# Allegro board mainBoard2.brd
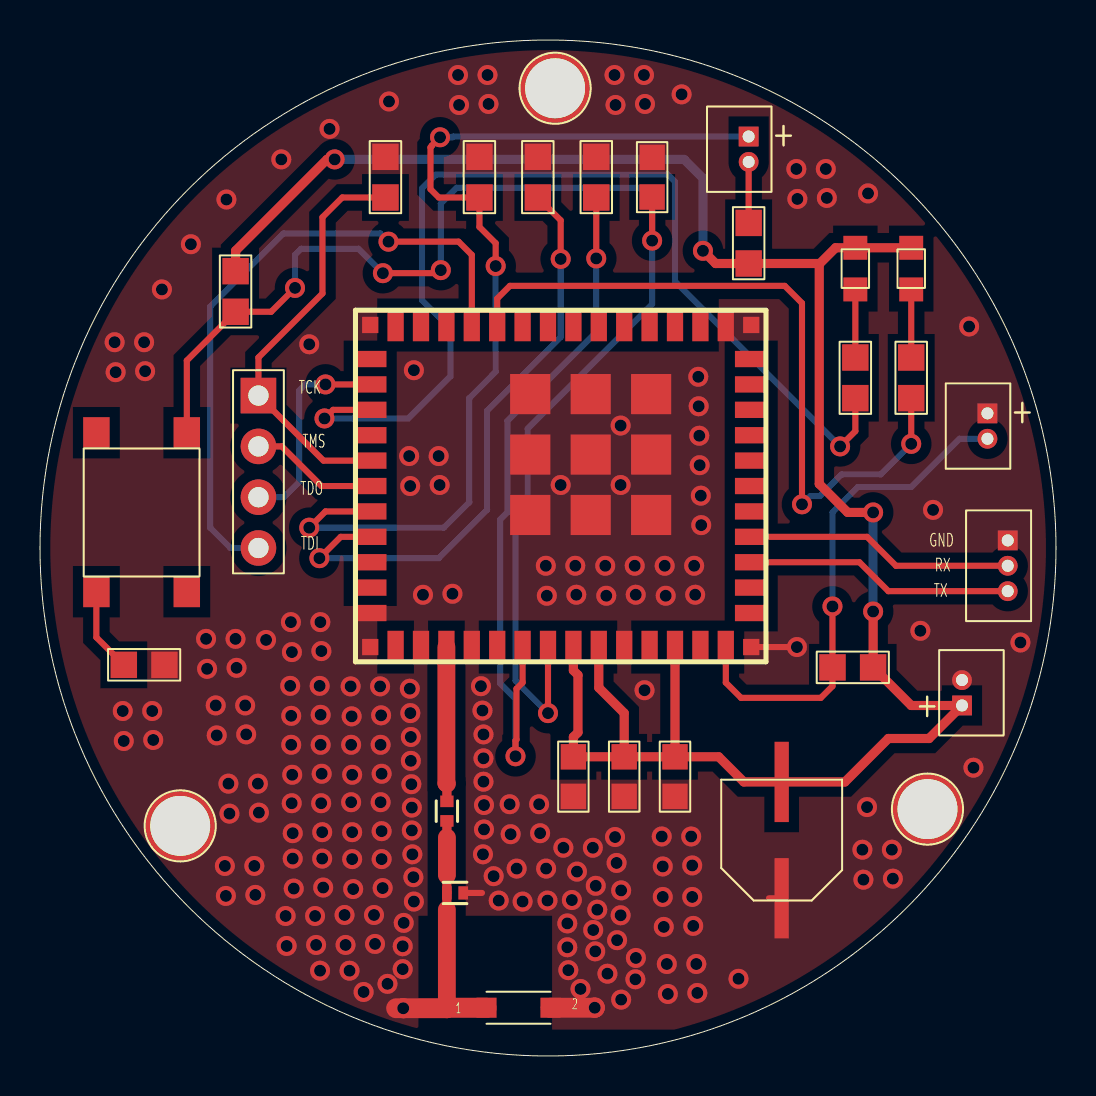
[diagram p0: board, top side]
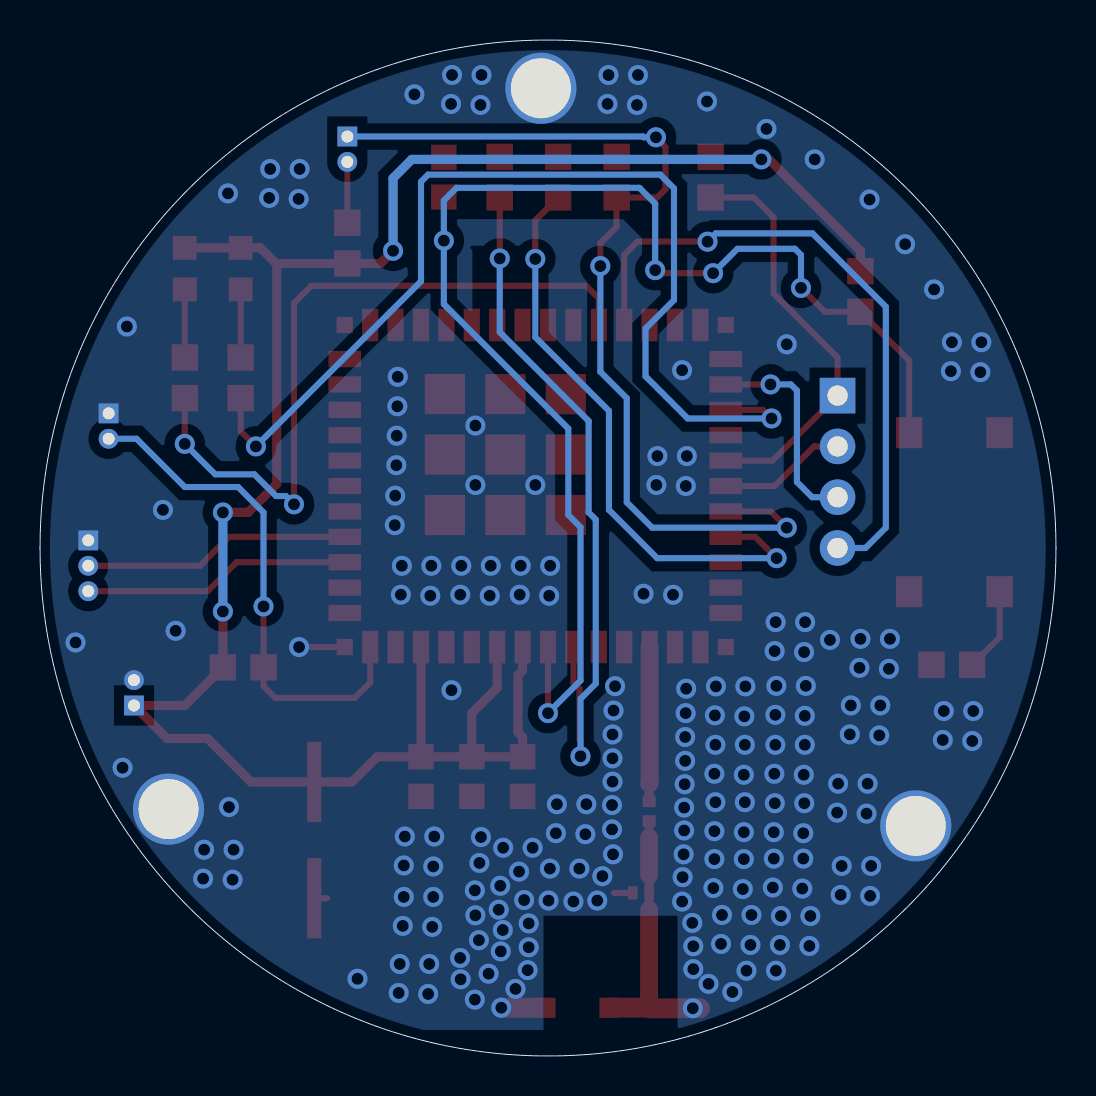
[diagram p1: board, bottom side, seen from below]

Outline 50.8 x 50.8 mm; copper layers: TOP, BOTTOM. Coordinates in mm from the lower left corner of the outline.
Outline path: circle c25.4,25.4 r25.4

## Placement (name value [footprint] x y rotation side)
C1  220uF/16V  [CAPPOL220U16V]  37.08 10.79 0 top
C2  0.1uF  [SMC0805]  29.21 13.97 270 top
C3  0.1uF  [SMC0805]  31.75 13.97 270 top
C4  1pF  [INDC_0402CS]  20.75 8.15 0 top
C5  0.1uF  [SMC0805]  30.61 43.94 90 top
C6  0.1uF  [SMC0805]  26.67 13.97 270 top
D1  -  [LED]  43.56 39.37 270 top
D2  -  [LED]  40.77 39.37 270 top
J1  HEADER 2  [HEADER21P25MM]  47.37 31.5 0 top
J2  HEADER 3  [HEADER31P25MM]  48.39 24.51 0 top
J3  HEADER 4  [HEADER42P54MM]  10.92 29.21 0 top
J4  HEADER 2  [HEADER21P25MM]  35.43 45.34 0 top
J5  HEADER 2  [HEADER21P25MM]  46.1 18.16 180 top
J6  HEADER 1  [HOLD]  44.37 12.34 0 top
J7  HEADER 1  [HOLD]  7.01 11.51 0 top
J8  HEADER 1  [HOLD]  25.76 48.39 0 top
L1  3.6nH  [CC0402]  20.35 12.24 270 top
R1  75  [SMR0805]  43.56 33.91 90 top
R2  75  [SMR0805]  40.77 33.91 90 top
R3  4.7K  [SMR0805]  9.78 38.23 270 top
R4  100R  [SMR0805]  5.21 19.56 0 top
R5  4.7K  [SMR0805]  35.43 40.64 90 top
R6  4.7K  [SMR0805]  40.64 19.43 180 top
R7  100K  [SMR0805]  17.27 43.94 90 top
R8  2.7K  [SMR0805]  21.97 43.94 90 top
R9  100K  [SMR0805]  24.89 43.94 90 top
R10  100K  [SMR0805]  27.81 43.94 90 top
S1  SW PUSHBUTTON  [BUTTON]  5.08 27.18 270 top
U1  -  [CC3200MOD]  35.56 20.45 0 top
U2  2.45-GHz Ant  [ANT_AH316M]  23.93 2.41 0 top

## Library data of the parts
C1 = CAPACITOR POL
C2-C6 = CAP NP
D1 D2 = LED_0
J1 J4 J5 = HEADER 2
J2 = HEADER 3
J3 = HEADER 4
J6-J8 = HEADER 1
L1 = INDUCTOR
R1-R4 R7-R10 = RESISTOR_0
R5 R6 = R
S1 = SW PUSHBUTTON
U1 = CC3200MOD_0
U2 = 2_0.45-GHz Ant

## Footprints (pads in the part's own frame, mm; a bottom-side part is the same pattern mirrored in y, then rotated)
ANT_AH316M
  rect 1.001x1.001 smd: 1(-1.6,0) 2(1.6,0)
BUTTON
  rect 1.549x1.321 smd: (-3.988,-2.261) (3.962,2.261) 1(-3.988,2.261) 2(3.962,-2.261)
CAPPOL220U16V
  rect 0.711x4.013 smd: 1(0,2.908) 2(0,-2.908)
CC0402
  rect 0.579x0.66 smd: 1(-0.49,0) 2(0.49,0)
CC3200MOD
  rect 0.813x0.813 smd: 1(0,16.104) 16(-19.05,16.104) 28(-19.05,0) 43(0,0)
  rect 0.813x1.626 smd: 2(-1.27,16.104) 3(-2.54,16.104) 4(-3.81,16.104) 5(-5.08,16.104) 6(-6.35,16.104) 7(-7.62,16.104) 8(-8.89,16.104) 9(-10.16,16.104) 10(-11.43,16.104) 11(-12.7,16.104) 12(-13.97,16.104) 13(-15.24,16.104) 14(-16.51,16.104) 15(-17.78,16.104) 29(-17.78,0) 30(-16.51,0) 31(-15.24,0) 32(-13.97,0) 33(-12.7,0) 34(-11.43,0) 35(-10.16,0) 36(-8.89,0) 37(-7.62,0) 38(-6.35,0) 39(-5.08,0) 40(-3.81,0) 41(-2.54,0) 42(-1.27,0)
  rect 1.626x0.813 smd: 17(-19.05,14.402) 18(-19.05,13.132) 19(-19.05,11.862) 20(-19.05,10.592) 21(-19.05,9.322) 22(-19.05,8.052) 23(-19.05,6.782) 24(-19.05,5.512) 25(-19.05,4.242) 26(-19.05,2.972) 27(-19.05,1.702) 44(0,1.702) 45(0,2.972) 46(0,4.242) 47(0,5.512) 48(0,6.782) 49(0,8.052) 50(0,9.322) 51(0,10.592) 52(0,11.862) 53(0,13.132) 54(0,14.402)
  rect 2.007x2.007 smd: 55(-5.004,12.649) 56(-8.026,12.649) 57(-11.049,12.649) 58(-5.004,9.627) 59(-8.026,9.627) 60(-11.049,9.627) 61(-5.004,6.604) 62(-8.026,6.604) 63(-11.049,6.604)
HEADER21P25MM
  rect 0.991x0.991 hole 0.599: 1(0,0.635)
  round 0.991 hole 0.599: 2(0,-0.635)
HEADER31P25MM
  rect 0.991x0.991 hole 0.599: 1(0,1.27)
  round 0.991 hole 0.599: 2(0,0) 3(0,-1.27)
HEADER42P54MM
  rect 1.778x1.778 hole 1.016: 1(0,3.81)
  round 1.778 hole 1.016: 2(0,1.27) 3(0,-1.27) 4(0,-3.81)
HOLD
  round 3.556 hole 2.997: 1(0,0)
INDC_0402CS
  rect 0.483x0.66 smd: 1(-0.409,0) 2(0.409,0)
LED
  rect 1.194x1.194 smd: 1(-1.041,0) 2(1.041,0)
SMC0805
  rect 1.27x1.27 smd: 1(-0.991,0) 2(0.991,0)
SMR0805
  rect 1.321x1.321 smd: 1(-1.016,0) 2(1.016,0)

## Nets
GND: C1.2 C2.2 C3.2 C4.1 C4.2 C5.2 C6.2 J1.1 J2.1 J5.2 J6.1 J7.1 J8.1 L1.2 R4.2 R7.2 R8.2 R9.2 R10.2 U1.1(GND2) U1.2(GND1) U1.16(GND18) U1.27(GND4) U1.28(GND7) U1.30(GND3) U1.32(GND8) U1.38(GND6) U1.43(GND5) U1.55(GND17) U1.56(GND16) U1.57(GND15) U1.58(GND14) U1.59(GND13) U1.60(GND12) U1.61(GND11) U1.62(GND10) U1.63(GND9) U2.1(IN) U2.2(GND)
VCC_3.3V: C1.1 C2.1 C3.1 C6.1 D1.1 D2.1 J5.1 R3.1 R5.1 R6.1 U1.36(VBAT_DCDC_ANA) U1.37(VBAT_DCDC_PA) U1.40(VBAT_DCDC_DIG_IO)
NLINK: R1.1 U1.11(GPIO22)
NREADY: R2.1 U1.19(GPIO28)
NRESET: C5.1 R3.2 S1.1 U1.35(NRESET)
SOP2: J4.1 R8.1 U1.23(TCXO_EN/SOP2)
SWITCH: J1.2 R6.2 U1.42(GPIO30)
UART0_RX: J2.2 U1.47(GPIO2)
UART0_TX: J2.3 U1.46(GPIO1)
N01152: R4.1 S1.2
N10829: J3.1 R7.1 U1.21(JTAG_TCK)
N10833: J3.2 U1.22(JTAG_TMS)
N10837: J3.3 U1.18(JTAG_TDO)
N10841: J3.4 U1.12(JTAG_TDI)
N12921: L1.1 U1.31(RF_BG)
N18108: R10.1 U1.34(SOP0)
N18112: R9.1 U1.24(SOP1)
N33058: J4.2 R5.2
N545706: D1.2 R1.2
N545710: D2.2 R2.2

Pads without a net: U1 3 4 5 6 7 8 9 10 13 14 15 17 20 25 26 29 33 39 41 44 45 48 49 50 51 52 53 54

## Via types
v1: diameter 1.001, hole 0.599, TOP to BOTTOM, 224 vias

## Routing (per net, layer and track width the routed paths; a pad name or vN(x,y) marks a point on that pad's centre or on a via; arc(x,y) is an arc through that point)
GND: length 20
  TOP w0.305: v1(37.85,20.45) U1.43 ; C4.2 22.1,8.15 ; 36.45,7.89 C1.2
  TOP w0.457: 20.35,9.04 20.34,9.04 C4.1 20.34,7.32 ; L1.2 20.35,10.92
  TOP w0.889: 20.35,10.92 20.35,9.04 ; 20.34,2.54 20.34,7.32
  TOP w0.991: 17.81,2.39 v1(18.16,2.39) 20.34,2.39 20.34,2.41 ; U2.2 v1(27.74,2.41) 27.74,2.44 ; 20.34,2.41 U2.1 ; 20.34,2.41 20.34,2.54
  vias: v1(3.73,35.69) v1(3.78,34.19) v1(4.14,17.25) v1(4.19,15.75) v1(5.2,35.69) v1(5.26,34.24) v1(5.61,17.25) v1(5.66,15.8) v1(6.1,38.33) v1(7.54,40.59) v1(8.3,20.86) v1(8.35,19.36) v1(8.79,17.53) v1(8.84,16.03) v1(9.24,9.5) v1(9.32,42.82) v1(9.29,8) v1(9.42,13.62) v1(9.47,12.12) v1(9.78,20.86) v1(9.83,19.41) v1(10.26,17.53) v1(10.31,16.08) v1(10.72,9.5) v1(10.77,8.05) v1(10.89,13.62) v1(10.94,12.17) v1(11.3,20.8) v1(12.06,44.83) v1(12.28,7) v1(12.33,5.5) v1(12.55,21.69) v1(12.51,18.51) v1(12.6,20.2) v1(12.56,17.01) v1(12.56,15.56) v1(12.61,14.06) v1(12.59,12.64) v1(12.64,11.14) v1(12.64,9.87) v1(12.69,8.37) v1(13.46,35.59) v1(13.75,7) v1(13.8,5.55) v1(14.02,21.69) v1(13.98,18.51) v1(14.03,17.06) v1(14.03,15.56) v1(14,4.26) v1(14.07,20.25) v1(14.08,14.11) v1(14.06,12.64) v1(14.11,11.19) v1(14.11,9.87) v1(14.16,8.42) v1(14.48,46.35) v1(15.23,7.05) v1(15.28,5.55) v1(15.53,18.48) v1(15.48,4.26) v1(15.58,16.98) v1(15.56,15.56) v1(15.61,14.06) v1(15.56,12.69) v1(15.61,11.19) v1(15.61,9.85) v1(15.66,8.35) v1(16.18,3.2) v1(16.7,7.05) v1(16.75,5.6) v1(17.01,18.48) v1(17.03,15.56) v1(17.03,12.69) v1(17.06,17.03) v1(17.08,14.11) v1(17.08,11.24) v1(17.08,9.85) v1(17.13,8.4) v1(17.45,47.73) v1(17.37,3.61) v1(18.14,5.49) v1(18.14,4.34) v1(18.19,6.65) v1(18.46,30) v1(18.51,28.5) v1(18.49,18.36) v1(18.52,17.14) v1(18.54,15.95) v1(18.54,14.76) v1(18.57,13.59) v1(18.59,12.42) v1(18.59,11.28) v1(18.62,10.08) v1(18.69,34.29) v1(18.67,8.94) v1(18.69,7.72) v1(19.15,23.06) v1(19.93,30) v1(19.98,28.55) v1(20.62,23.11) v1(20.9,49.05) v1(20.95,47.55) v1(22.05,18.49) v1(22.12,17.27) v1(22.15,10.08) v1(22.17,16.08) v1(22.17,14.88) v1(22.17,13.72) v1(22.2,12.55) v1(22.2,11.33) v1(22.37,49.05) v1(22.43,47.6) v1(22.68,8.99) v1(22.94,7.77) v1(23.48,12.59) v1(23.53,11.09) v1(23.83,9.37) v1(24.13,7.72) v1(24.96,12.59) v1(25.01,11.14) v1(25.29,24.51) v1(25.34,23.01) v1(25.31,9.37) v1(25.37,7.77) v1(26.04,28.55) v1(26.17,10.41) v1(26.37,6.63) v1(26.37,5.44) v1(26.42,4.29) v1(26.59,7.8) v1(26.76,24.51) v1(26.81,23.06) v1(26.85,9.22) v1(27.03,3.35) v1(27.64,10.41) v1(27.66,6.3) v1(27.79,8.51) v1(27.76,5.23) v1(27.86,7.32) v1(28.26,24.51) v1(28.31,23.01) v1(28.37,4.11) v1(28.72,49.05) v1(28.78,47.55) v1(28.75,10.95) v1(28.83,9.65) v1(28.85,5.79) v1(29.03,31.52) v1(29.03,28.55) v1(29.03,7.04) v1(29.06,8.28) v1(29.06,2.82) v1(29.74,24.51) v1(29.79,23.06) v1(29.79,4.9) v1(29.77,3.84) v1(30.2,49.05) v1(30.25,47.6) v1(30.23,18.29) v1(31.09,10.98) v1(31.14,9.48) v1(31.14,7.95) v1(31.23,24.51) v1(31.19,6.45) v1(31.29,23.01) v1(31.34,4.6) v1(31.39,3.1) v1(32.08,48.08) v1(32.56,10.98) v1(32.61,9.53) v1(32.61,7.95) v1(32.71,24.51) v1(32.66,6.5) v1(32.76,23.06) v1(32.81,4.6) v1(32.91,33.96) v1(32.93,32.49) v1(32.87,3.15) v1(32.96,31.01) v1(32.98,29.54) v1(33.04,28.02) v1(33.06,26.54) v1(34.92,3.86) v1(37.82,44.35) v1(37.87,42.85) v1(39.29,44.35) v1(39.34,42.9) v1(41.12,10.31) v1(41.17,8.82) v1(41.4,43.13) v1(41.35,12.45) v1(42.59,10.31) v1(42.64,8.87) v1(44.02,21.26) v1(44.65,27.3) v1(46.46,36.47) v1(46.67,14.41) v1(49.02,20.68)
VCC_3.3V: length 107.3
  TOP w0.457: 38.96,39.6 38.96,28.6 40.39,27.18 v1(41.66,27.18) ; 38.96,39.6 39.78,40.41 D2.1 D1.1 ; 38.96,39.6 38.94,39.62 R5.1 33.78,39.62 v1(33.15,40.26) ; U1.37 27.94,18.41 29.21,17.14 C2.1 ; U1.40 C3.1 ; C3.1 33.93,14.96 35.19,13.7 C1.1 40.25,13.7 42.42,15.87 44.45,15.87 J5.1 43.56,17.53 R6.1 v1(41.66,22.22) ; C3.1 C2.1 ; v1(14.73,44.83) 14.35,44.83 9.78,40.26 R3.1 ; C2.1 C6.1 26.67,15.95 26.9,16.18 26.9,19.05 26.67,19.28 U1.36
  BOTTOM w0.457: v1(33.15,40.26) 33.15,43.89 32.21,44.83 v1(14.73,44.83) ; v1(41.66,22.22) v1(41.66,27.18)
NLINK: length 36.2
  TOP w0.305: U1.11 22.86,37.87 23.49,38.51 37.24,38.51 38.1,37.64 v1(38.1,27.58) ; v1(43.56,30.61) R1.1
  BOTTOM w0.305: v1(43.56,30.61) 42.04,29.08 40.08,29.08 39,28 38.51,28 v1(38.1,27.58)
NREADY: length 52.1
  TOP w0.305: v1(40,30.48) 40.77,31.24 R2.1 ; v1(14.22,31.88) 14.66,32.31 U1.19
  BOTTOM w0.305: v1(40,30.48) 31.75,38.73 31.75,43.71 31.39,44.07 19.79,44.07 19.1,43.38 19.1,37.8 20.52,36.37 20.52,33.99 18.41,31.88 v1(14.22,31.88)
NRESET: length 69.3
  TOP w0.305: v1(12.75,38.4) 11.56,37.21 R3.2 7.34,34.77 S1.1 ; v1(17.14,39.14) 19.89,39.14 v1(20.04,39.29) ; v1(30.61,40.77) C5.1 ; U1.35 v1(25.4,17.14)
  BOTTOM w0.305: v1(25.4,17.14) 23.77,18.77 23.77,26.44 24.38,27.05 24.38,31.37 30.61,37.59 v1(30.61,40.77) 30.61,42.77 29.97,43.41 20.83,43.41 20.04,42.62 v1(20.04,39.29) ; v1(17.14,39.14) 15.93,40.36 13.06,40.36 12.75,40.06 v1(12.75,38.4)
SOP2: length 48.9
  TOP w0.305: v1(22.78,39.5) 22.78,40.64 21.97,41.45 R8.1 19.94,42.93 19.52,43.34 19.52,45.43 19.59,45.5 19.59,45.52 v1(20,45.94) ; v1(13.46,26.42) 14.27,27.23 U1.23
  BOTTOM w0.305: v1(20,45.94) 20.61,45.94 20.65,45.97 J4.1 ; v1(22.78,39.5) 22.78,34.21 21.46,32.89 21.46,27.69 20.19,26.42 v1(13.46,26.42)
SWITCH: length 25.6
  TOP w0.305: v1(39.62,22.48) R6.2 39.62,18.49 39.04,17.91 35.05,17.91 34.29,18.67 U1.42
  BOTTOM w0.305: v1(39.62,22.48) 39.62,27.18 40.89,28.45 43.56,28.45 45.97,30.86 J1.2
UART0_RX: length 13.4
  TOP w0.305: U1.47 41.35,25.96 42.8,24.51 J2.2
UART0_TX: length 13.4
  TOP w0.305: U1.46 40.97,24.69 42.42,23.24 J2.3
N01152: length 4.2
  TOP w0.305: 4.19,19.56 2.82,20.93 S1.2
N10829: length 20.7
  TOP w0.305: U1.21 14.17,29.77 J3.1 10.92,34.92 14.12,38.13 14.12,41.94 15.11,42.93 R7.1
N10833: length 6.4
  TOP w0.305: J3.2 12.09,30.48 14.07,28.5 U1.22
N10837: length 10.6
  TOP w0.305: U1.18 v1(14.27,33.58)
  BOTTOM w0.305: v1(14.27,33.58) 13.26,33.58 12.95,33.27 12.95,28.7 12.19,27.94 J3.3
N10841: length 32.4
  TOP w0.305: U1.12 21.59,40.06 20.93,40.72 v1(17.42,40.72)
  BOTTOM w0.305: J3.4 9.52,25.4 8.51,26.42 8.51,37.46 12.17,41.13 17.01,41.13 v1(17.42,40.72)
N12921: length 7.7
  TOP w0.457: 20.35,13.61 L1.1
  TOP w0.889: U1.31 20.32,13.64 20.35,13.61
N18108: length 35.9
  TOP w0.305: v1(27.81,39.88) R10.1 ; v1(23.77,14.99) 23.77,15.77 23.83,15.82 23.83,18.36 24.13,18.67 U1.34
  BOTTOM w0.305: v1(27.81,39.88) 27.81,36.2 23.37,31.75 23.37,27.18 23.01,26.82 23.01,18.62 23.77,17.86 v1(23.77,14.99)
N18112: length 30
  TOP w0.305: v1(13.97,24.89) 15.04,25.96 U1.24 ; R9.1 26.04,41.78 v1(26.04,39.85)
  BOTTOM w0.305: v1(26.04,39.85) 26.04,35.94 22.35,32.26 22.35,27.3 19.94,24.89 v1(13.97,24.89)
N33058: length 3
  TOP w0.305: R5.2 J4.2
N545706: length 3.4
  TOP w0.305: R1.2 D1.2
N545710: length 3.4
  TOP w0.305: R2.2 D2.2

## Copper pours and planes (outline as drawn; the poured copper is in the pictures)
GND on TOP: 25.6,1.32 25.6,7.01 21.29,7.01 21.29,13.94 19.38,13.94 19.38,7.01 18.92,7.01 18.92,1.37 25.5,50.29 31.72,1.32 ; 7 cut-outs
GND on BOTTOM: 25.63,1.3 25.63,7.01 18.92,7.01 18.92,1.37 25.55,50.29 31.62,1.3 ; 5 cut-outs

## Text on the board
Ref Des/Silkscreen Top: TCK | TDO | TDI | TMS | GND | TX | RX
